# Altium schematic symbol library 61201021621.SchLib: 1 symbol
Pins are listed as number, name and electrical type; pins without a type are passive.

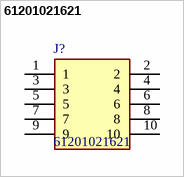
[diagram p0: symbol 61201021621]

## 61201021621
designator J?
10 way 2.54mm male box Header Wurth Elektronik 612 Series, 2.54mm Pitch 10 Way 2 Row Straight PCB Header, Solder Termination, 3A; Geometry.Height: 9.25mm
footprint SHDR10W64P254_2X5_2036X885X925P
pins: 1, 2, 3, 4, 5, 6, 7, 8, 9, 10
